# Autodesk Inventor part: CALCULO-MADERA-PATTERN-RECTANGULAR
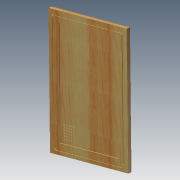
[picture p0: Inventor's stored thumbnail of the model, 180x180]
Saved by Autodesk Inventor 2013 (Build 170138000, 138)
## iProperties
Created: 2012-03
Part Number: CALCULO-MADERA-PATTERN-RECTANGULAR
Material: Generic
Document SubType Name: Modeling
Designer: julian.chica
Mass: 462.834 g
Surface Area: 1534.07 cm^2
Volume: 462.834 cm^3
Density: 1 g/cm^3
Author: julian.chica
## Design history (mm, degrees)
node "XZ- Plane Front"
sketch "Sketch7"
  geometry: L1 (-100, 150)-(100, 150); L2 (100, 150)-(100, -150); L3 (100, -150)-(-100, -150); L4 (-100, -150)-(-100, 150); 3 further points
  constraints: 8 end point, 2 midpoint, 2 parallel, 1 horizontal, 1 horizontal alignment, 1 perpendicular, 1 vertical alignment
  dimensions: "d4" = 300 distance of L1.end L2.end; "d5" = 200 distance of L1.start L1.end
extrude "Extrusion1" new body sketch "Sketch7" stored distance "d6" = 10; taper "d7" = 0 deg
sketch "Sketch8"
  geometry: L1 (100, 150)-(100, -150) reference; L2 (-100, 150)-(100, 150) reference; L3 (-100, -150)-(-100, 150) reference; L4 (100, -150)-(-100, -150) reference; L5 (75, 125)-(75, -125); L6 (75, -125)-(-75, -125); L7 (-75, -125)-(-75, 125); L8 (-75, 125)-(75, 125); 1 further point
  constraints: 8 end point, 3 other
  dimensions: "d8" = 25 distance between parallel lines of L3 L7
extrude "Extrusion2" cut sketch "Sketch8" distance "d9" = 3; taper "d10" = 0 deg
sketch "Sketch9"
  geometry: L1 (-75, 125)-(75, 125) reference; L2 (75, 125)-(75, -125) reference; L3 (75, -125)-(-75, -125) reference; L4 (-75, -125)-(-75, 125) reference; L5 (-82, 142)-(82, 142); L6 (92, 132)-(92, -132); L7 (82, -142)-(-82, -142); L8 (-92, -132)-(-92, 132); L9 (-87, 132)-(-87, -132); L10 (-82, -137)-(82, -137); L11 (87, -132)-(87, 132); L12 (82, 137)-(-82, 137); A1 r 10 centre (-82, 132) between (-82, 142) and (-92, 132); A2 r 10 centre (82, 132) between (92, 132) and (82, 142); A3 r 10 centre (-82, -132) between (-92, -132) and (-82, -142); A4 r 10 centre (82, -132) between (82, -142) and (92, -132); A5 r 5 centre (-82, -132) between (-87, -132) and (-82, -137); A6 r 5 centre (82, -132) between (82, -137) and (87, -132); A7 r 5 centre (82, 132) between (87, 132) and (82, 137); A8 r 5 centre (-82, 132) between (-82, 137) and (-87, 132); 1 further point
  constraints: 16 end point, 16 point on circle, 8 centre point, 8 tangent, 3 equal radius, 10 other
  dimensions: "d11" = 17 distance between parallel lines of L5 L1; "d12" = 10 radius of A1; "d13" = 5 distance between parallel lines of L8 L9
extrude "Extrusion3" cut sketch "Sketch9" distance "d14" = 2; taper "d15" = 0 deg
sketch "Sketch10"
  geometry: L1 (-75, 125)-(-75, -125) reference; L2 (-75, -125)-(75, -125) reference; C1 r 1.5 at (-65, -115); 1 further point
  constraints: 1 centre point
  dimensions: "DISTANCIA_B" = 10 distance from line of C1.centre L2; "DISTANCIA_A" = 10 distance from line of L1 C1.centre; "d18" = 3 diameter of C1
extrude "Extrusion4" cut sketch "Sketch10" distance "d19" = 10; taper "d20" = 0 deg
sketch "Sketch11"
  geometry: L1 (-82, -137)-(82, -137) reference; L2 (87, -132)-(87, 132) reference; L3 (82, 137)-(-82, 137) reference; L4 (-87, 132)-(-87, -132) reference; L5 (-75, 125)-(75, 125) reference; L6 (75, 125)-(75, -125) reference; L7 (75, -125)-(-75, -125) reference; L8 (-75, -125)-(-75, 125) reference; A1 r 5 centre (-82, -132) between (-87, -132) and (-82, -137) reference; A2 r 5 centre (82, -132) between (82, -137) and (87, -132) reference; A3 r 5 centre (82, 132) between (87, 132) and (82, 137) reference; A4 r 5 centre (-82, 132) between (-82, 137) and (-87, 132) reference; 1 further point
  dimensions: "d27" = 12 distance between parallel lines of L2 L6 (derived)
body "Solid1"
pattern_linear "Rectangular Pattern1" dims "DISTANCIA_C" = 6, "DISTANCIA_D" = 6
other parameters: "d0" = 0
